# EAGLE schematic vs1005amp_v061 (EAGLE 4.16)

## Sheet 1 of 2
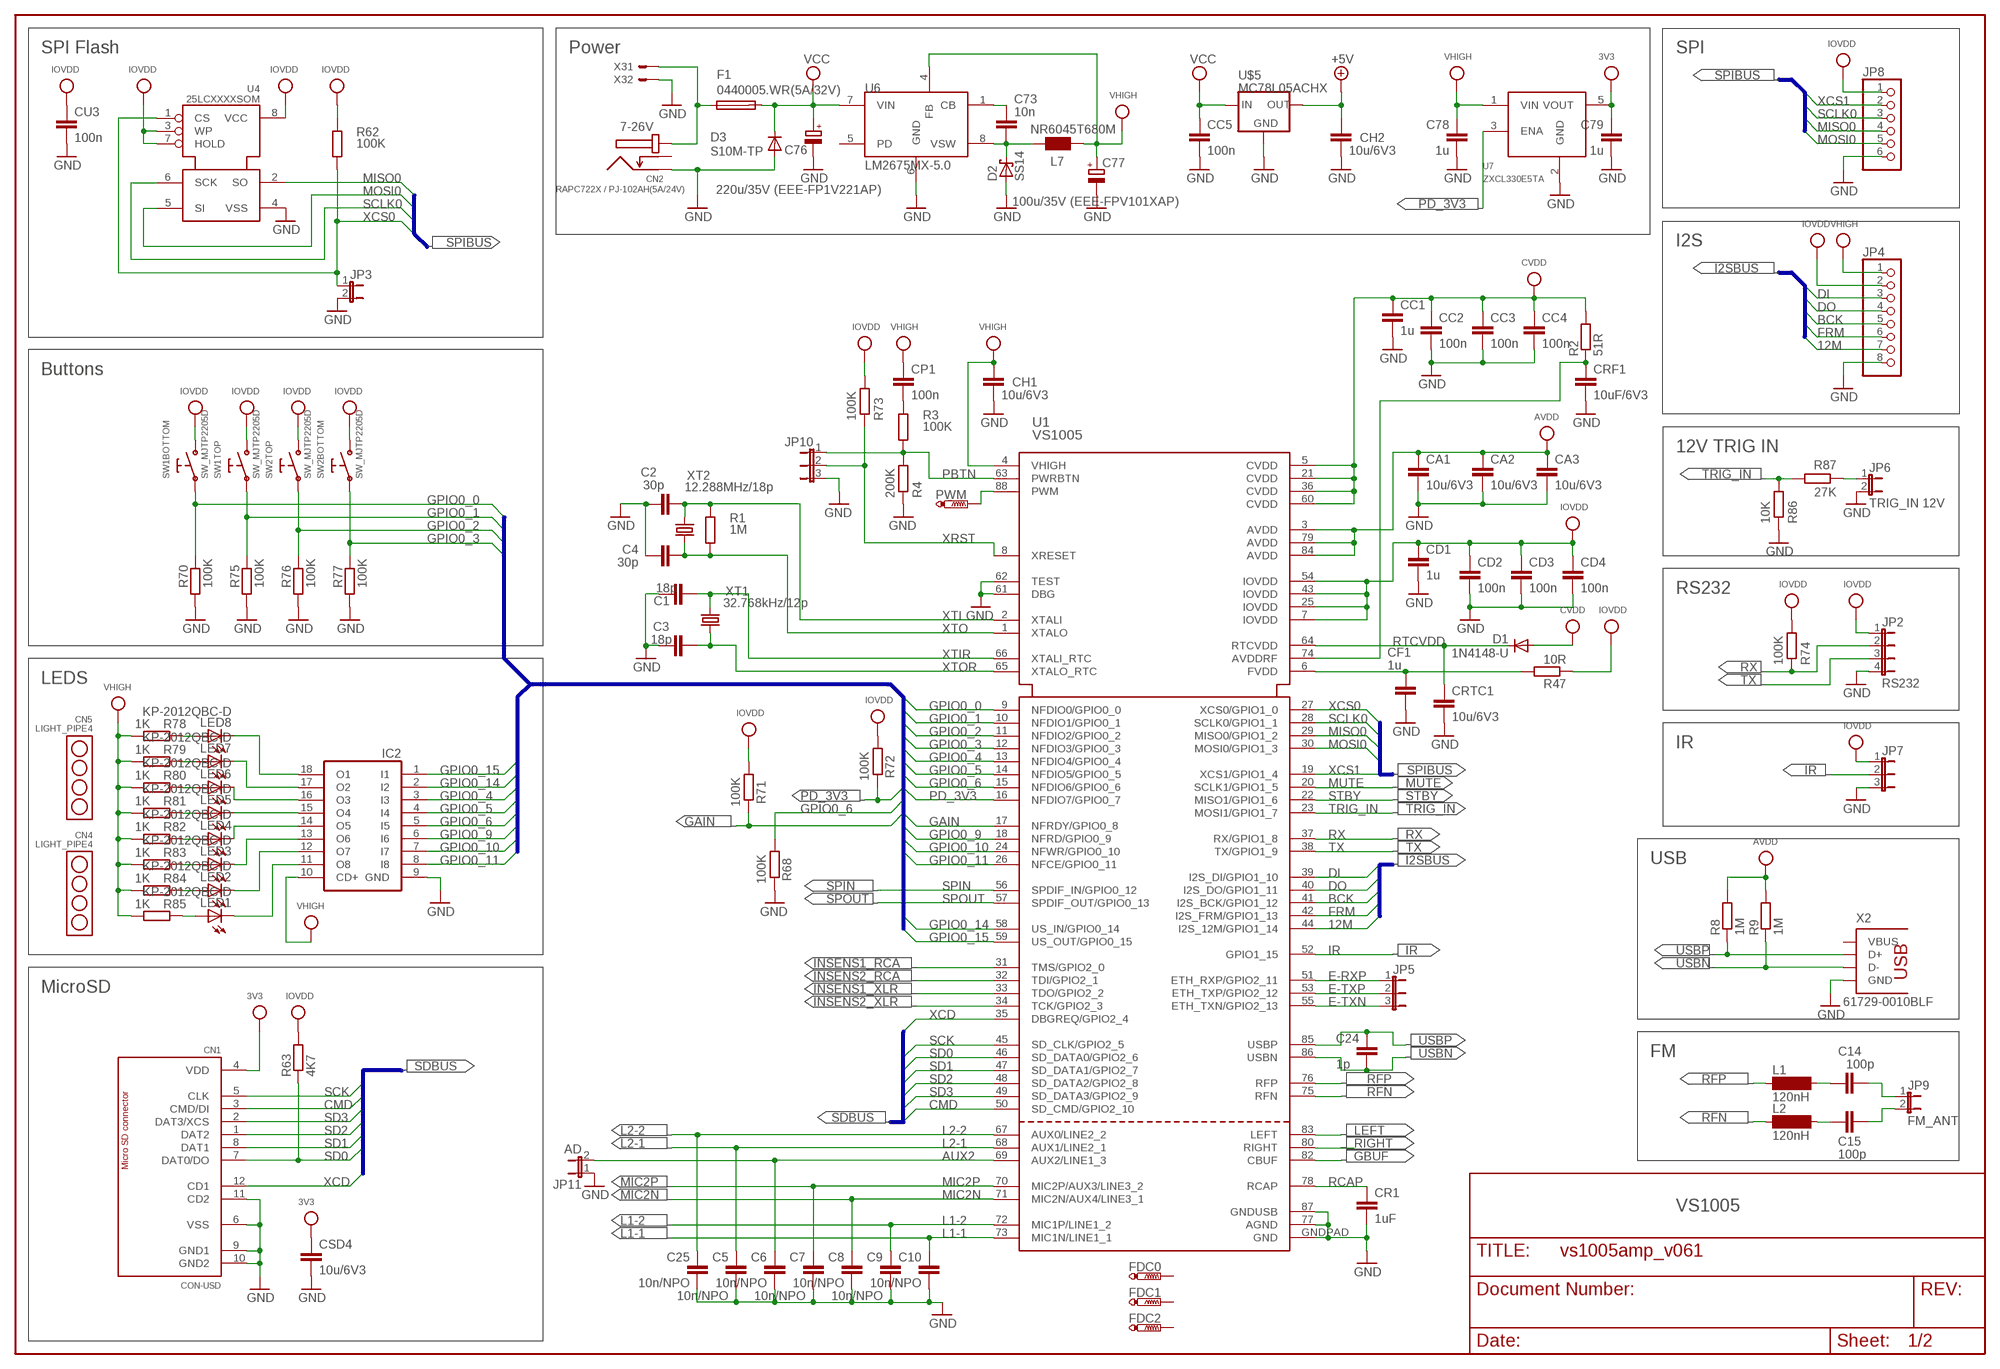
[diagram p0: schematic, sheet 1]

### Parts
C1  18p  C-EUC0603  [C0603]
C2  30p  C-EUC0603  [C0603]
C3  18p  C-EUC0603  [C0603]
C4  30p  C-EUC0603  [C0603]
C5  10n/NPO  C-EUC0805  [C0805]
C6  10n/NPO  C-EUC0805  [C0805]
C7  10n/NPO  C-EUC0805  [C0805]
C8  10n/NPO  C-EUC0805  [C0805]
C9  10n/NPO  C-EUC0805  [C0805]
C10  10n/NPO  C-EUC0805  [C0805]
C14  100p  C-EUC0603  [C0603]
C15  100p  C-EUC0603  [C0603]
C24  1p  C-EUC0603  [C0603]
C25  10n/NPO  C-EUC0805  [C0805]
C73  10n  C-EUC0603  [C0603]
C76  220u/35V (EEE-FP1V221AP)  CPOL-EUF  [PANASONIC_F]
C77  100u/35V (EEE-FPV101XAP)  CPOL-EUD  [PANASONIC_D]
C78  1u  C-EUC0603  [C0603]
C79  1u  C-EUC0603  [C0603]
CA1  10u/6V3  C-EUC0603  [C0603]
CA2  10u/6V3  C-EUC0603  [C0603]
CA3  10u/6V3  C-EUC0603  [C0603]
CC1  1u  C-EUC0603  [C0603]
CC2  100n  C-EUC0603  [C0603]
CC3  100n  C-EUC0603  [C0603]
CC4  100n  C-EUC0603  [C0603]
CC5  100n  C-EUC0603  [C0603]
CD1  1u  C-EUC0603  [C0603]
CD2  100n  C-EUC0603  [C0603]
CD3  100n  C-EUC0603  [C0603]
CD4  100n  C-EUC0603  [C0603]
CF1  1u  C-EUC0603  [C0603]
CH1  10u/6V3  C-EUC0603  [C0603]
CH2  10u/6V3  C-EUC0603  [C0603]
CN1  CON-USD  [MSSN09-A0-300]
CN2  RAPC722X / PJ-102AH(5A/24V)  CON_DC-JACK  [DC-JACK]
CN4  LIGHT_PIPE4  [LIGHT_PIPE4]
CN5  LIGHT_PIPE4  [LIGHT_PIPE4]
CP1  100n  C-EUC0603  [C0603]
CR1  1uF  C-EUC0603  [C0603]
CRF1  10uF/6V3  C-EUC0603  [C0603]
CRTC1  10u/6V3  C-EUC0603  [C0603]
CSD4  10u/6V3  C-EUC0603  [C0603]
CU3  100n  C-EUC0603  [C0603]
D1  1N4148-U  [MICROMELF-W]
D2  SS14  SS12-SMA  [DO214AC]
D3  S10M-TP  DIODE-DO214BA  [DO214BA]
F1  0440005.WR(5A/32V)  FUSE_1206  [R1206]
FDC0  PTR1TP10R  [TP10R]
FDC1  PTR1TP10R  [TP10R]
FDC2  PTR1TP10R  [TP10R]
IC2  ULN2803AADWR  [SO18L]
JP2  RS232  JP4E  [JP4]
JP3  JP1E  [JP1]
JP4  PINHD-1X8  [1X08]
JP5  JP2E  [JP2]
JP6  TRIG_IN 12V  JP1E  [JP1]
JP7  JP2E  [JP2]
JP8  PINHD-1X6  [1X06]
JP9  FM_ANT  JP1E  [JP1]
JP10  JP2E  [JP2]
JP11  AD  JP1E  [JP1]
L1  120nH  SM-0603  [0603]
L2  120nH  SM-0603  [0603]
L7  NR6045T680M  L_NR6045  [L_NR6045]
LED1  KP-2012QBC-D  LEDCHIPLED_0805  [CHIPLED_0805]
LED2  KP-2012QBC-D  LEDCHIPLED_0805  [CHIPLED_0805]
LED3  KP-2012QBC-D  LEDCHIPLED_0805  [CHIPLED_0805]
LED4  KP-2012QBC-D  LEDCHIPLED_0805  [CHIPLED_0805]
LED5  KP-2012QBC-D  LEDCHIPLED_0805  [CHIPLED_0805]
LED6  KP-2012QBC-D  LEDCHIPLED_0805  [CHIPLED_0805]
LED7  KP-2012QBC-D  LEDCHIPLED_0805  [CHIPLED_0805]
LED8  KP-2012QBC-D  LEDCHIPLED_0805  [CHIPLED_0805]
PWM  PTR1TP10R  [TP10R]
R1  1M  R-EU_R0603  [R0603]
R2  51R  R-EU_R0603  [R0603]
R3  100K  R-EU_R0603  [R0603]
R4  200K  R-EU_R0603  [R0603]
R8  1M  R-EU_R0603  [R0603]
R9  1M  R-EU_R0603  [R0603]
R47  10R  R-EU_R0603  [R0603]
R62  100K  R-EU_R0603  [R0603]
R63  4K7  R-EU_R0603  [R0603]
R68  100K  R-EU_R0603  [R0603]
R70  100K  R-EU_R0603  [R0603]
R71  100K  R-EU_R0603  [R0603]
R72  100K  R-EU_R0603  [R0603]
R73  100K  R-EU_R0603  [R0603]
R74  100K  R-EU_R0603  [R0603]
R75  100K  R-EU_R0603  [R0603]
R76  100K  R-EU_R0603  [R0603]
R77  100K  R-EU_R0603  [R0603]
R78  1K  R-EU_R0603  [R0603]
R79  1K  R-EU_R0603  [R0603]
R80  1K  R-EU_R0603  [R0603]
R81  1K  R-EU_R0603  [R0603]
R82  1K  R-EU_R0603  [R0603]
R83  1K  R-EU_R0603  [R0603]
R84  1K  R-EU_R0603  [R0603]
R85  1K  R-EU_R0603  [R0603]
R86  10K  R-EU_R0603  [R0603]
R87  27K  R-EU_R0603  [R0603]
SW1  SW_MJTP2205D  [SW_MJTP2205D]
SW2  SW_MJTP2205D  [SW_MJTP2205D]
U1  VS1005  [QFN88_2]
U4  25LCXXXXSOM  [SO-8MN]
U6  LM2675MX-5.0  LM2675  [SO08]
U7  ZXCL330E5TA  ZXCL280E5TA  [SOT23-5L]
U$5  MC78L05ACHX  UA78LXX  [SOT89]
X2  61729-0010BLF  CON_USB_B@N  [PN61729]
X3  1935161  TER_BLOCK_2WAY  [TER_BLOCK-2-WAY]
XT1  32.768kHz/12p  CRYSTAL3.2X1.5MM  [CRYSTAL_1206]
XT2  12.288MHz/18p  CRYTALHC49UP  [HC49UP]

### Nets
1: CN2.1 F1.1 X3.P$1
3V3: C79.1 CN1.4(VDD) CSD4.1 U7.5(VOUT) ; also sheet 2
12M: JP4.7 U1.44(I2S_12M/GPIO1_14)
+5V: CH2.1 U$5.1(OUT) ; also sheet 2
AUX2: C6.1 JP11.2 U1.69(AUX2/LINE1_3)
AVDD: CA1.1 CA2.1 CA3.1 R8.2 R9.2 U1.3(AVDD) U1.79(AVDD) U1.84(AVDD) ; also sheet 2
AVDDRF: CRF1.1 R2.1 U1.74(AVDDRF)
BCK: JP4.5 U1.41(I2S_BCK/GPIO1_12)
CMD: CN1.3(CMD/DI) U1.50(SD_CMD/GPIO2_10)
CVDD: CC1.1 CC2.1 CC3.1 CC4.1 D1.A R2.2 U1.5(CVDD) U1.21(CVDD) U1.36(CVDD) U1.60(CVDD)
DI: JP4.3 U1.39(I2S_DI/GPIO1_10)
DO: JP4.4 U1.40(I2S_DO/GPIO1_11)
E-RXP: JP5.1 U1.51(ETH_RXP/GPIO2_11)
E-TXN: JP5.3 U1.55(ETH_TXN/GPIO2_13)
E-TXP: JP5.2 U1.53(ETH_TXP/GPIO2_12)
FRM: JP4.6 U1.42(I2S_FRM/GPIO1_13)
FVDD: CF1.1 R47.2 U1.6(FVDD)
GAIN: R71.2 U1.17(NFRDY/GPIO0_8) ; also sheet 2
GBUF: U1.82(CBUF) ; also sheet 2
GND: C1.1 C2.1 C3.1 C4.1 C5.2 C6.2 C7.2 C8.2 C9.2 C10.2 C25.2 C76.- C77.- C78.2 C79.2 CA1.2 CA2.2 CA3.2 CC1.2 CC2.2 CC3.2 CC4.2 CC5.2 CD1.2 CD2.2 CD3.2 CD4.2 CF1.2 CH1.2 CH2.2 CN1.6(VSS) CN1.9(GND1) CN1.10(GND2) CN1.11(CD2) CN2.3 CR1.2 CRF1.2 CRTC1.2 CSD4.2 CU3.2 D2.A D3.A IC2.9(GND) JP2.4 JP3.2 JP4.8 JP6.2 JP7.3 JP8.6 JP10.3 JP11.1 R4.2 R68.1 R70.2 R75.2 R76.2 R77.2 R86.2 U1.61(DBG) U1.62(TEST) U1.77(AGND) U1.87(GNDUSB) U1.GNDPAD(GND) U4.4(VSS) U6.6(GND) U7.2(GND) U$5.2(GND) X2.4(GND) X3.P$2 ; also sheet 2
GPIO0_0: R70.1 SW1.2 U1.9(NFDIO0/GPIO0_0)
GPIO0_1: R75.1 SW1.1 U1.10(NFDIO1/GPIO0_1)
GPIO0_2: R76.1 SW2.1 U1.11(NFDIO2/GPIO0_2)
GPIO0_3: R77.1 SW2.2 U1.12(NFDIO3/GPIO0_3)
GPIO0_4: IC2.3(I3) U1.13(NFDIO4/GPIO0_4)
GPIO0_5: IC2.4(I4) U1.14(NFDIO5/GPIO0_5)
GPIO0_6: IC2.5(I5) R68.2 U1.15(NFDIO6/GPIO0_6)
GPIO0_9: IC2.6(I6) U1.18(NFRD/GPIO0_9)
GPIO0_10: IC2.7(I7) U1.24(NFWR/GPIO0_10)
GPIO0_11: IC2.8(I8) U1.26(NFCE/GPIO0_11)
GPIO0_14: IC2.2(I2) U1.58(US_IN/GPIO0_14)
GPIO0_15: IC2.1(I1) U1.59(US_OUT/GPIO0_15)
INSENS1_RCA: U1.31(TMS/GPIO2_0) ; also sheet 2
INSENS1_XLR: U1.33(TDO/GPIO2_2) ; also sheet 2
INSENS2_RCA: U1.32(TDI/GPIO2_1) ; also sheet 2
INSENS2_XLR: U1.34(TCK/GPIO2_3) ; also sheet 2
IOVDD: CD1.1 CD2.1 CD3.1 CD4.1 CU3.1 JP2.1 JP4.2 JP7.1 JP8.1 R47.1 R62.1 R63.2 R71.1 R72.1 R73.1 R74.1 SW1.3 SW1.4 SW2.3 SW2.4 U1.7(IOVDD) U1.25(IOVDD) U1.43(IOVDD) U1.54(IOVDD) U4.3(WP) U4.7(HOLD) U4.8(VCC)
IR: JP7.2 U1.52(GPIO1_15)
L1-1: C10.1 U1.73(MIC1N/LINE1_1) ; also sheet 2
L1-2: C9.1 U1.72(MIC1P/LINE1_2) ; also sheet 2
L2-1: C5.1 U1.68(AUX1/LINE2_1) ; also sheet 2
L2-2: C25.1 U1.67(AUX0/LINE2_2) ; also sheet 2
LEFT: U1.83(LEFT) ; also sheet 2
MIC2N: C8.1 U1.71(MIC2N/AUX4/LINE3_1) ; also sheet 2
MIC2P: C7.1 U1.70(MIC2P/AUX3/LINE3_2) ; also sheet 2
MISO0: JP8.4 U1.29(MISO0/GPIO1_2) U4.2(SO)
MOSI0: JP8.5 U1.30(MOSI0/GPIO1_3) U4.5(SI)
MUTE: U1.20(SCLK1/GPIO1_5) ; also sheet 2
N$1: C14.1 L1.2
N$3: CP1.2 R3.1
N$28: LED8.A R78.2
N$60: C14.2 JP9.1
N$67: C73.1 U6.1(CB)
N$68: C73.2 D2.C L7.1 U6.8(VSW)
N$69: LED7.A R79.2
N$70: LED6.A R80.2
N$72: LED5.A R81.2
N$73: LED4.A R82.2
N$75: LED3.A R83.2
N$76: LED2.A R84.2
N$77: LED1.A R85.2
N$78: IC2.11(O8) LED1.C
N$79: IC2.12(O7) LED2.C
N$81: IC2.13(O6) LED3.C
N$82: IC2.14(O5) LED4.C
N$83: IC2.15(O4) LED5.C
N$84: IC2.16(O3) LED6.C
N$85: IC2.17(O2) LED7.C
N$86: IC2.18(O1) LED8.C
N$87: JP6.1 R87.2
N$88: C15.2 JP9.2
N$103: C15.1 L2.2
PBTN: JP10.1 R3.2 R4.1 U1.63(PWRBTN)
PD_3V3: R72.2 U1.16(NFDIO7/GPIO0_7) U7.3(ENA)
PWM: PWM.TP U1.88(PWM)
RCAP: CR1.1 U1.78(RCAP) ; also sheet 2
RFN: L2.1 U1.75(RFN)
RFP: L1.1 U1.76(RFP)
RIGHT: U1.80(RIGHT) ; also sheet 2
RTCVDD: CRTC1.1 D1.C U1.64(RTCVDD)
RX: JP2.2 R74.2 U1.37(RX/GPIO1_8)
SCK: CN1.5(CLK) U1.45(SD_CLK/GPIO2_5)
SCLK0: JP8.3 U1.28(SCLK0/GPIO1_1) U4.6(SCK)
SD0: CN1.7(DAT0/DO) R63.1 U1.46(SD_DATA0/GPIO2_6)
SD1: CN1.8(DAT1) U1.47(SD_DATA1/GPIO2_7)
SD2: CN1.1(DAT2) U1.48(SD_DATA2/GPIO2_8)
SD3: CN1.2(DAT3/XCS) U1.49(SD_DATA3/GPIO2_9)
SPIN: U1.56(SPDIF_IN/GPIO0_12) ; also sheet 2
SPOUT: U1.57(SPDIF_OUT/GPIO0_13) ; also sheet 2
STBY: U1.22(MISO1/GPIO1_6) ; also sheet 2
TRIG_IN: R86.1 R87.1 U1.23(MOSI1/GPIO1_7)
TX: JP2.3 U1.38(TX/GPIO1_9)
USBN: C24.2 R9.1 U1.86(USBN) X2.2(D-)
USBP: C24.1 R8.1 U1.85(USBP) X2.3(D+)
VCC: C76.+ CC5.1 D3.C F1.2 U6.7(VIN) U$5.3(IN) ; also sheet 2
VHIGH: C77.+ C78.1 CH1.1 CP1.1 IC2.10(CD+) JP4.1 L7.2 R78.1 R79.1 R80.1 R81.1 R82.1 R83.1 R84.1 R85.1 U1.4(VHIGH) U6.4(FB) U7.1(VIN)
XCD: CN1.12(CD1) U1.35(DBGREQ/GPIO2_4)
XCS0: JP3.1 R62.2 U1.27(XCS0/GPIO1_0) U4.1(CS)
XCS1: JP8.2 U1.19(XCS1/GPIO1_4)
XRST: JP10.2 R73.2 U1.8(XRESET)
XTI: C2.2 R1.1 U1.2(XTALI) XT2.2
XTIR: C1.2 U1.66(XTALI_RTC) XT1.2
XTO: C4.2 R1.2 U1.1(XTALO) XT2.1
XTOR: C3.2 U1.65(XTALO_RTC) XT1.1
Unconnected: CN2.2 FDC0.TP FDC1.TP FDC2.TP U6.5(PD) X2.1(VBUS)

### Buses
NFBUS:GPIO0_[0..11],GPIO0_[14..15]
SDBUS:SCK,SD[0..3],CMD,XCD
SPIBUS:XCS1,XCS0,SCLK0,MISO0,MOSI0
I2SBUS:DI,DO,BCK,FRM,12M

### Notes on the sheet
- SPI Flash | Power | SPI
- SPIBUS
- 7-26V
- SPIBUS
- I2S
- I2SBUS
- Buttons
- 12V TRIG IN
- RS232
- LEDS
- IR
- SPIBUS
- I2SBUS | USB
- MicroSD
- FM
- SDBUS
- SDBUS
- VS1005

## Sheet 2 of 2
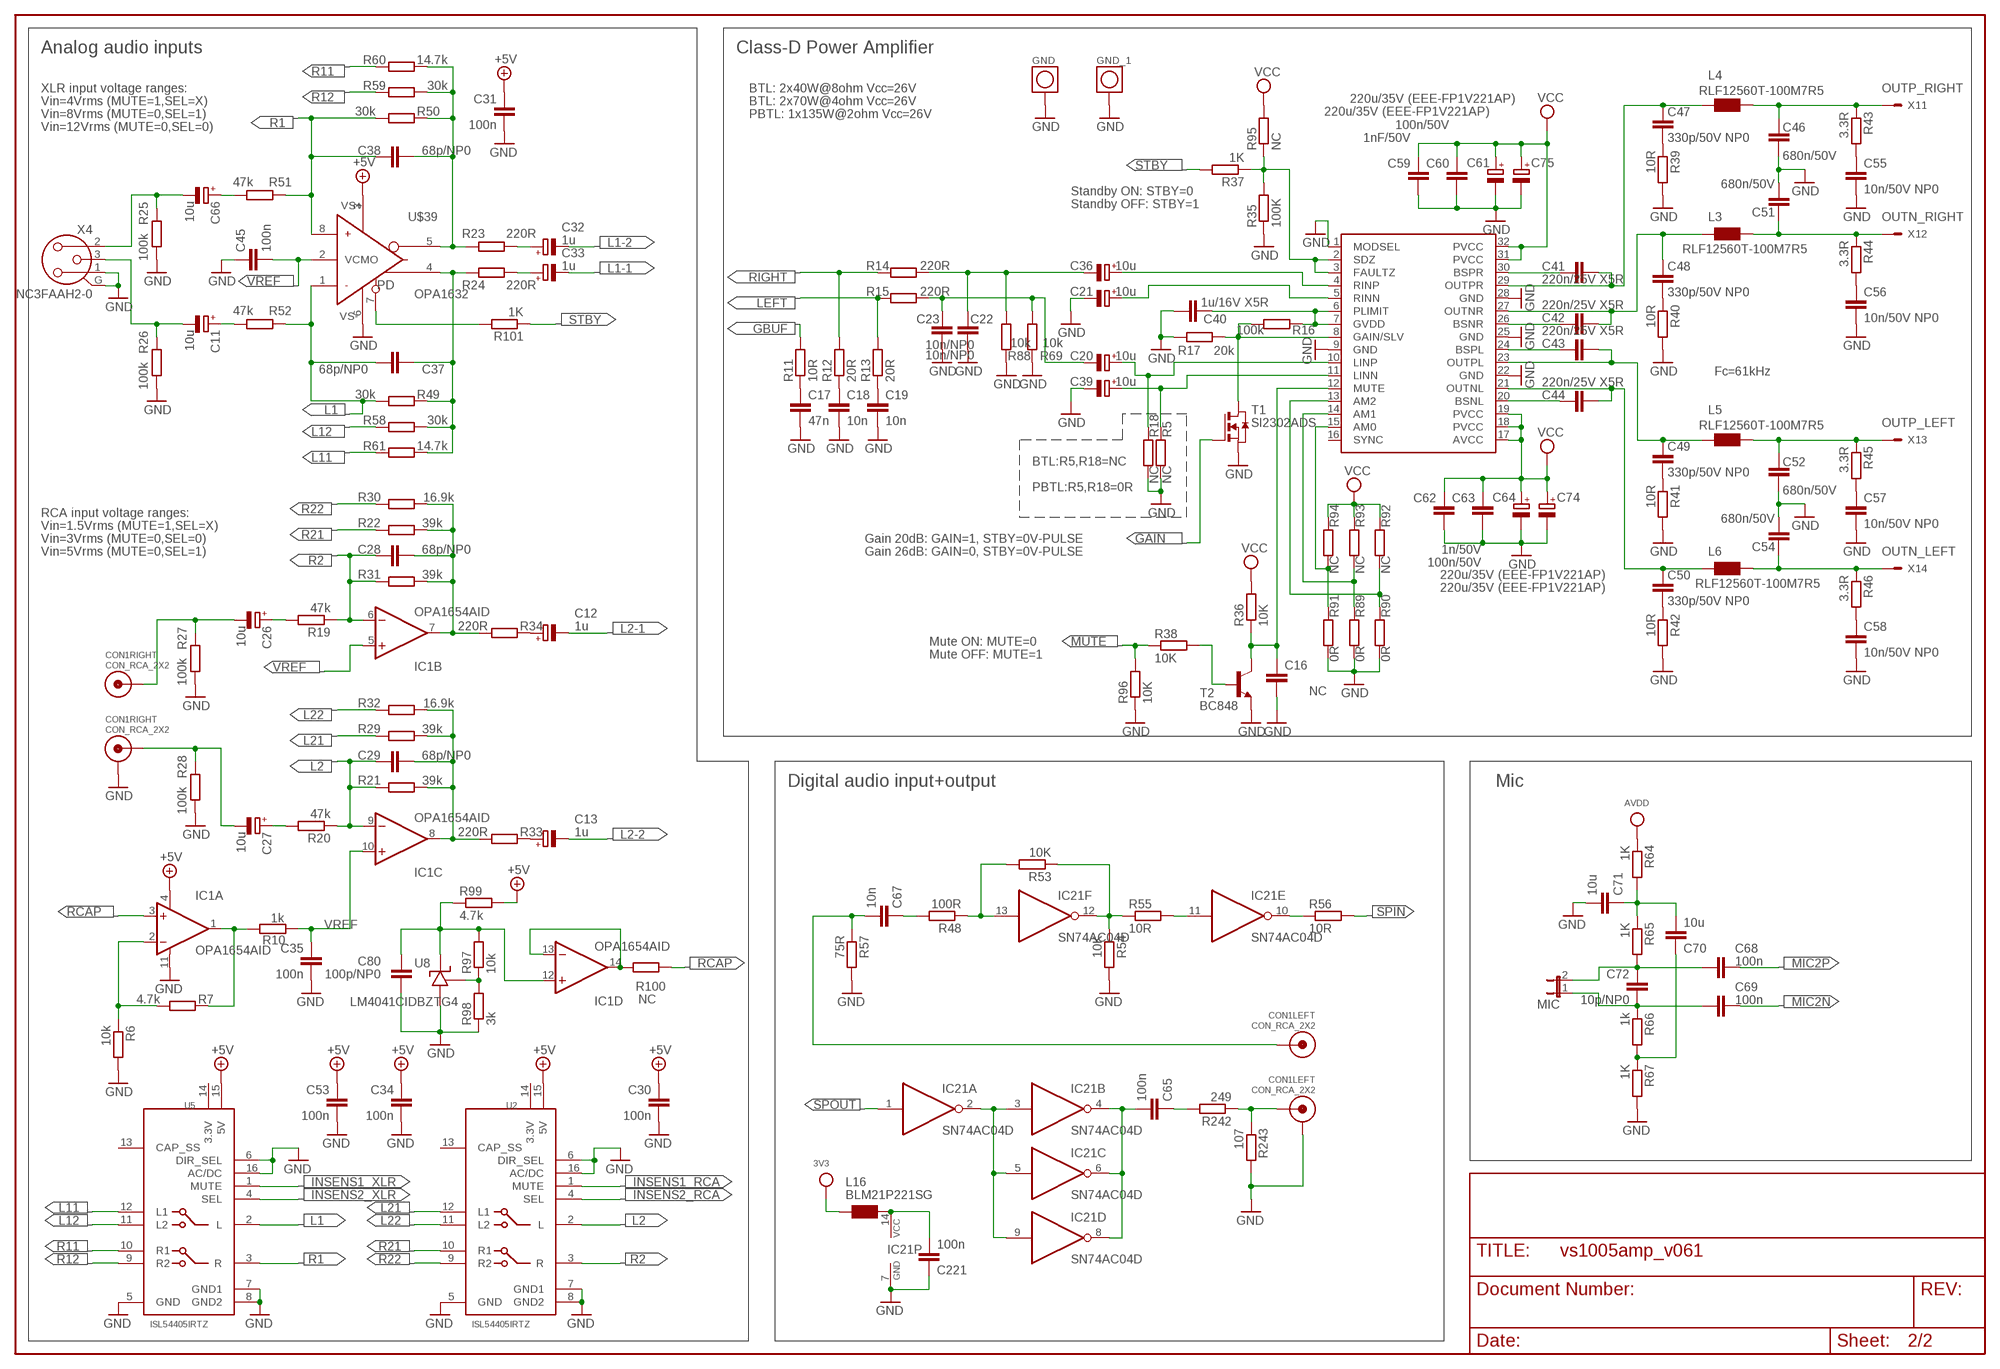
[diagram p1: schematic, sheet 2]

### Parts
C11  10u  CPOL-EUB  [PANASONIC_B]
C12  1u  CPOL-EU153CLV-0405  [153CLV-0405]
C13  1u  CPOL-EU153CLV-0405  [153CLV-0405]
C16  NC  C-EUC0603  [C0603]
C17  47n  C-EUC0603  [C0603]
C18  10n  C-EUC0603  [C0603]
C19  10n  C-EUC0603  [C0603]
C20  10u  CPOL-EUB  [PANASONIC_B]
C21  10u  CPOL-EUB  [PANASONIC_B]
C22  10n/NP0  C-EUC0805  [C0805]
C23  10n/NP0  C-EUC0805  [C0805]
C26  10u  CPOL-EUB  [PANASONIC_B]
C27  10u  CPOL-EUB  [PANASONIC_B]
C28  68p/NP0  C-EUC0805  [C0805]
C29  68p/NP0  C-EUC0805  [C0805]
C30  100n  C-EUC0603  [C0603]
C31  100n  C-EUC0603  [C0603]
C32  1u  CPOL-EU153CLV-0405  [153CLV-0405]
C33  1u  CPOL-EU153CLV-0405  [153CLV-0405]
C34  100n  C-EUC0603  [C0603]
C35  100n  C-EUC0603  [C0603]
C36  10u  CPOL-EUB  [PANASONIC_B]
C37  68p/NP0  C-EUC0805  [C0805]
C38  68p/NP0  C-EUC0805  [C0805]
C39  10u  CPOL-EUB  [PANASONIC_B]
C40  1u/16V X5R  C-EUC0603  [C0603]
C41  220n/25V X5R  C-EUC0603  [C0603]
C42  220n/25V X5R  C-EUC0603  [C0603]
C43  220n/25V X5R  C-EUC0603  [C0603]
C44  220n/25V X5R  C-EUC0603  [C0603]
C45  100n  C-EUC0603  [C0603]
C46  680n/50V  C-EUC1206  [C1206]
C47  330p/50V NP0  C-EUC0603  [C0603]
C48  330p/50V NP0  C-EUC0603  [C0603]
C49  330p/50V NP0  C-EUC0603  [C0603]
C50  330p/50V NP0  C-EUC0603  [C0603]
C51  680n/50V  C-EUC1206  [C1206]
C52  680n/50V  C-EUC1206  [C1206]
C53  100n  C-EUC0603  [C0603]
C54  680n/50V  C-EUC1206  [C1206]
C55  10n/50V NP0  C-EUC0805  [C0805]
C56  10n/50V NP0  C-EUC0805  [C0805]
C57  10n/50V NP0  C-EUC0805  [C0805]
C58  10n/50V NP0  C-EUC0805  [C0805]
C59  1nF/50V  C-EUC0603  [C0603]
C60  100n/50V  C-EUC0603  [C0603]
C61  220u/35V (EEE-FP1V221AP)  CPOL-EUF  [PANASONIC_F]
C62  1n/50V  C-EUC0603  [C0603]
C63  100n/50V  C-EUC0603  [C0603]
C64  220u/35V (EEE-FP1V221AP)  CPOL-EUF  [PANASONIC_F]
C65  100n  C-EUC0603  [C0603]
C66  10u  CPOL-EUB  [PANASONIC_B]
C67  10n  C-EUC0603  [C0603]
C68  100n  C-EUC0603  [C0603]
C69  100n  C-EUC0603  [C0603]
C70  10u  C-EUC0805  [C0805]
C71  10u  C-EUC0805  [C0805]
C72  10p/NP0  C-EUC0603  [C0603]
C74  220u/35V (EEE-FP1V221AP)  CPOL-EUF  [PANASONIC_F]
C75  220u/35V (EEE-FP1V221AP)  CPOL-EUF  [PANASONIC_F]
C80  100p/NP0  C-EUC0603K  [C0603K]
C221  100n  C-EUC0603  [C0603]
CON1  CON_RCA_2X2  [4XRCA_2X2]
GND  MEAS_PIN  [MEAS_PIN]
GND_1  MEAS_PIN  [MEAS_PIN]
IC1  OPA1654AID  OPA4132U  [SO14]
IC21  SN74AC04D  74AC04D  [SO14]
L3  RLF12560T-100M7R5  L_12560  [RLF12560]
L4  RLF12560T-100M7R5  L_12560  [RLF12560]
L5  RLF12560T-100M7R5  L_12560  [RLF12560]
L6  RLF12560T-100M7R5  L_12560  [RLF12560]
L16  BLM21P221SG  WE-KI_0805_B  [WE-KI_0805_B]
MIC  JP1E  [JP1]
R5  NC  R-EU_R0603  [R0603]
R6  10k  R-EU_R0603  [R0603]
R7  4.7k  R-EU_R0603  [R0603]
R10  1k  R-EU_R0603  [R0603]
R11  10R  R-EU_R0603  [R0603]
R12  20R  R-EU_R0603  [R0603]
R13  20R  R-EU_R0603  [R0603]
R14  220R  R-EU_R0603  [R0603]
R15  220R  R-EU_R0603  [R0603]
R16  100k  R-EU_R0603  [R0603]
R17  20k  R-EU_R0603  [R0603]
R18  NC  R-EU_R0603  [R0603]
R19  47k  R-EU_R0603  [R0603]
R20  47k  R-EU_R0603  [R0603]
R21  39k  R-EU_R0603  [R0603]
R22  39k  R-EU_R0603  [R0603]
R23  220R  R-EU_R0603  [R0603]
R24  220R  R-EU_R0603  [R0603]
R25  100k  R-EU_R0603  [R0603]
R26  100k  R-EU_R0603  [R0603]
R27  100k  R-EU_R0603  [R0603]
R28  100k  R-EU_R0603  [R0603]
R29  39k  R-EU_R0603  [R0603]
R30  16.9k  R-EU_R0603  [R0603]
R31  39k  R-EU_R0603  [R0603]
R32  16.9k  R-EU_R0603  [R0603]
R33  220R  R-EU_R0603  [R0603]
R34  220R  R-EU_R0603  [R0603]
R35  100K  R-EU_R0603  [R0603]
R36  10K  R-EU_R0603  [R0603]
R37  1K  R-EU_R0603  [R0603]
R38  10K  R-EU_R0603  [R0603]
R39  10R  R-EU_R0805  [R0805]
R40  10R  R-EU_R0805  [R0805]
R41  10R  R-EU_R0805  [R0805]
R42  10R  R-EU_R0805  [R0805]
R43  3.3R  R-EU_R0805  [R0805]
R44  3.3R  R-EU_R0805  [R0805]
R45  3.3R  R-EU_R0805  [R0805]
R46  3.3R  R-EU_R0805  [R0805]
R48  100R  R-EU_R0603  [R0603]
R49  30k  R-EU_R0603  [R0603]
R50  30k  R-EU_R0603  [R0603]
R51  47k  R-EU_R0603  [R0603]
R52  47k  R-EU_R0603  [R0603]
R53  10K  R-EU_R0603  [R0603]
R54  10K  R-EU_R0603  [R0603]
R55  10R  R-EU_R0603  [R0603]
R56  10R  R-EU_R0603  [R0603]
R57  75R  R-EU_R0603  [R0603]
R58  30k  R-EU_R0603  [R0603]
R59  30k  R-EU_R0603  [R0603]
R60  14.7k  R-EU_R0603  [R0603]
R61  14.7k  R-EU_R0603  [R0603]
R64  1K  R-EU_R0603  [R0603]
R65  1K  R-EU_R0603  [R0603]
R66  1k  R-EU_R0603  [R0603]
R67  1K  R-EU_R0603  [R0603]
R69  10k  R-EU_R0603  [R0603]
R88  10k  R-EU_R0603  [R0603]
R89  0R  R-EU_R0603  [R0603]
R90  0R  R-EU_R0603  [R0603]
R91  0R  R-EU_R0603  [R0603]
R92  NC  R-EU_R0603  [R0603]
R93  NC  R-EU_R0603  [R0603]
R94  NC  R-EU_R0603  [R0603]
R95  NC  R-EU_R0603  [R0603]
R96  10K  R-EU_R0603  [R0603]
R97  10k  R-EU_R0603  [R0603]
R98  3k  R-EU_R0603  [R0603]
R99  4.7k  R-EU_R0603  [R0603]
R100  NC  R-EU_R0603  [R0603]
R101  1K  R-EU_R0603  [R0603]
R242  249  R-EU_R1206  [R1206]
R243  107  R-EU_R1206  [R1206]
T1  SI2302ADS  [SOT23]
T2  BC848  [SOT23]
U2  ISL54405IRTZ  ISL54405  [QFN16]
U3  TPA3116D2  [HTSSOP32]
U5  ISL54405IRTZ  ISL54405  [QFN16]
U8  LM4041CIDBZTG4  LM4041CI  [SOT23@1]
U$39  OPA1632  THS4130  [SO08]
X1  1935187  TER_BLOCK_4WAY  [TER_BLOCK-4-WAY]
X4  NC3FAAH2-0  NC3FAH2  [NC3FAH2]

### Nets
3V3: L16.1 ; also sheet 1
+5V: C30.1 C31.1 C34.1 C53.1 IC1.4(A:V+) R99.2 U2.15(5V) U5.15(5V) U$39.3(VS+) ; also sheet 1
AVDD: R64.1 ; also sheet 1
GAIN: T1.1(G) ; also sheet 1
GBUF: R11.2 ; also sheet 1
GND: C16.2 C17.2 C18.2 C19.2 C21.- C22.2 C23.2 C30.2 C31.2 C34.2 C35.2 C39.- C40.2 C45.1 C46.2 C51.2 C52.2 C53.2 C54.2 C55.2 C56.2 C57.2 C58.2 C59.2 C60.2 C61.- C62.2 C63.2 C64.- C71.2 C74.- C75.- C80.2 C221.1 CON1.GL(LEFT:RING) CON1.GR(RIGHT:RING) GND.P$1 GND_1.P$1 IC1.11(A:V-) IC21.7(P:GND) R5.2 R6.2 R17.2 R18.2 R25.1 R26.1 R27.1 R28.1 R35.1 R39.2 R40.2 R41.2 R42.2 R54.2 R57.2 R67.2 R69.2 R88.2 R89.2 R90.2 R91.2 R96.1 R98.1 R243.2 T1.2(S) T2.2(E) U2.5(GND) U2.6(DIR_SEL) U2.7(GND1) U2.8(GND2) U2.16(AC/DC) U3.1(MODSEL) U3.9(GND) U3.22(GND) U3.25(GND) U3.28(GND) U5.5(GND) U5.6(DIR_SEL) U5.7(GND1) U5.8(GND2) U5.16(AC/DC) U8.3(A) U$39.6(VS-) X4.1 X4.G ; also sheet 1
INSENS1_RCA: U2.1(MUTE) ; also sheet 1
INSENS1_XLR: U5.1(MUTE) ; also sheet 1
INSENS2_RCA: U2.4(SEL) ; also sheet 1
INSENS2_XLR: U5.4(SEL) ; also sheet 1
L1: C37.2 R49.1 R52.2 U5.2(L) U$39.1(-IN)
L1-1: C33.- ; also sheet 1
L1-2: C32.- ; also sheet 1
L2: C29.1 IC1.9(C:-IN) R20.1 R21.2 U2.2(L)
L2-1: C12.- ; also sheet 1
L2-2: C13.- ; also sheet 1
L11: R61.2 U5.12(L1)
L12: R58.2 U5.11(L2)
L21: R29.2 U2.12(L1)
L22: R32.2 U2.11(L2)
L222: C37.1 R24.1 R49.2 R58.1 R61.1 U$39.4(+OUT)
LEFT: R13.2 R15.2 ; also sheet 1
MIC2N: C69.1 ; also sheet 1
MIC2P: C68.1 ; also sheet 1
MUTE: R38.1 R96.2 ; also sheet 1
N$2: C27.+ R20.2
N$4: C26.+ R19.2
N$6: C29.2 IC1.8(C:OUT) R21.1 R29.1 R32.1 R33.1
N$7: C28.2 IC1.7(B:OUT) R22.1 R30.1 R31.1 R34.1
N$8: C66.- R25.2 X4.2
N$9: C11.- R26.2 X4.3
N$11: C32.+ R23.2
N$12: R38.2 T2.1(B)
N$13: R97.1 R98.2 U8.1(FB)
N$14: C33.+ R24.2
N$15: R101.2 U$39.7
N$16: R35.2 R37.1 R95.1 U3.2(SDZ) U3.3(FAULTZ)
N$17: C26.- CON1.WR(RIGHT:TIP1) R27.2
N$18: C19.1 R13.1
N$19: C27.- CON1.RR(RIGHT:TIP) R28.2
N$20: C13.+ R33.2
N$21: C18.1 R12.1
N$22: C17.1 R11.1
N$23: C12.+ R34.2
N$24: C69.2 C72.2 MIC.1 R66.1
N$26: C68.2 C72.1 MIC.2 R65.2
N$27: C70.2 C71.1 R64.2 R65.1
N$29: C21.+ U3.5(RINN)
N$30: IC1.2(A:-IN) R6.1 R7.1
N$31: C36.+ U3.4(RINP)
N$32: C16.1 R36.1 T2.3(C) U3.12(MUTE)
N$33: IC1.1(A:OUT) R7.2 R10.1
N$34: C70.1 R66.2 R67.1
N$35: R16.2 R17.1 T1.3(D) U3.8(GAIN/SLV)
N$36: C80.1 IC1.12(D:+IN) R97.2 R99.1 U8.2(C)
N$37: C41.2 U3.30(BSPR)
N$38: C42.2 U3.26(BSNR)
N$39: C42.1 C48.1 L3.1 U3.27(OUTNR)
N$40: IC1.13(D:-IN) IC1.14(D:OUT) R100.1
N$41: C43.2 U3.24(BSPL)
N$42: C43.1 C49.1 L5.1 U3.23(OUTPL)
N$43: C44.1 C50.1 L6.1 U3.21(OUTNL)
N$44: C44.2 U3.20(BSNL)
N$45: C40.1 R16.1 U3.6(PLIMIT) U3.7(GVDD)
N$46: IC21.2(A:O) IC21.3(B:I) IC21.5(C:I) IC21.9(D:I)
N$47: C20.- C23.1 R15.1 R69.1
N$49: C47.2 R39.1
N$50: C48.2 R40.1
N$51: C49.2 R41.1
N$52: C50.2 R42.1
N$53: C41.1 C47.1 L4.1 U3.29(OUTPR)
N$54: C65.2 IC21.4(B:O) IC21.6(C:O) IC21.8(D:O)
N$55: C65.1 R242.2
N$56: C67.2 CON1.WL(LEFT:TIP1) R57.1
N$57: C55.1 R43.2
N$58: C56.1 R44.2
N$59: C67.1 R48.2
N$61: C57.1 R45.2
N$62: C58.1 R46.2
N$63: IC21.13(F:I) R48.1 R53.2
N$64: IC21.12(F:O) R53.1 R54.1 R55.1
N$65: IC21.11(E:I) R55.2
N$66: IC21.10(E:O) R56.1
N$74: C66.+ R51.1
N$80: C11.+ R52.1
N$89: C22.1 C36.- R14.1 R88.1
N$90: R89.1 R93.2 U3.14(AM1)
N$119: R91.1 R94.2 U3.15(AM0)
N$120: R90.1 R92.2 U3.13(AM2)
N$121: C39.+ R5.1 U3.11(LINN)
N$122: C20.+ R18.1 U3.10(LINP)
N$232: CON1.RL(LEFT:TIP) R242.1 R243.1
N$245: C221.2 IC21.14(P:VCC) L16.2
OUTN_LEFT: C54.1 L6.2 R46.1 X1.P$4
OUTN_RIGHT: C51.1 L3.2 R44.1 X1.P$2
OUTP_LEFT: C52.1 L5.2 R45.1 X1.P$1
OUTP_RIGHT: C46.1 L4.2 R43.1 X1.P$3
R1: C38.1 R50.1 R51.2 U5.3(R) U$39.8(+IN)
R2: C28.1 IC1.6(B:-IN) R19.1 R31.2 U2.3(R)
R11: R60.2 U5.10(R1)
R12: R59.2 U5.9(R2)
R21: R22.2 U2.10(R1)
R22: R30.2 U2.9(R2)
R2222: C38.2 R23.1 R50.2 R59.1 R60.1 U$39.5(-OUT)
RCAP: IC1.3(A:+IN) R100.2 ; also sheet 1
RIGHT: R12.2 R14.2 ; also sheet 1
SPIN: R56.2 ; also sheet 1
SPOUT: IC21.1(A:I) ; also sheet 1
STBY: R37.2 R101.1 ; also sheet 1
VCC: C59.1 C60.1 C61.+ C62.1 C63.1 C64.+ C74.+ C75.+ R36.2 R92.1 R93.1 R94.1 R95.2 U3.17(AVCC) U3.18(PVCC) U3.19(PVCC) U3.31(PVCC) U3.32(PVCC) ; also sheet 1
VREF: C35.1 C45.2 IC1.5(B:+IN) IC1.10(C:+IN) R10.2 U$39.2(VOCM)
Unconnected: U2.13(CAP_SS) U2.14(3.3V) U3.16(SYNC) U5.13(CAP_SS) U5.14(3.3V)

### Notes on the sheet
- Analog audio inputs | Class-D Power Amplifier
- XLR input voltage ranges: | BTL: 2x40W@8ohm Vcc=26V
- Vin=4Vrms (MUTE=1,SEL=X) | BTL: 2x70W@4ohm Vcc=26V
- Vin=8Vrms (MUTE=0,SEL=1) | PBTL: 1x135W@2ohm Vcc=26V
- Vin=12Vrms (MUTE=0,SEL=0)
- Standby ON: STBY=0
- Standby OFF: STBY=1
- Fc=61kHz
- BTL:R5,R18=NC
- PBTL:R5,R18=0R
- RCA input voltage ranges:
- Vin=1.5Vrms (MUTE=1,SEL=X)
- Vin=3Vrms (MUTE=0,SEL=0) | Gain 20dB: GAIN=1, STBY=0V-PULSE
- Vin=5Vrms (MUTE=0,SEL=1) | Gain 26dB: GAIN=0, STBY=0V-PULSE
- Mute ON: MUTE=0
- Mute OFF: MUTE=1
- Digital audio input+output | Mic

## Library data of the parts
C1-C10 C14-C19 C22-C25 C28-C31 C34 C35 C37 C38 C40-C60 C62 C63 C65 C67-C73 C78-C80 C221 CA1-CA3 CC1-CC5 CD1-CD4 CF1 CH1 CH2 CP1 CR1 CRF1 CRTC1 CSD4 CU3 = rcl:C-EU: CAPACITOR, European symbol
C11-C13 C20 C21 C26 C27 C32 C33 C36 C39 C61 C64 C66 C74-C77 = rcl:CPOL-EU: POLARIZED CAPACITOR, European symbol
CN1 = Omat:CON-USD: Micro SD connector
CN2 = Omat_komponentit:CON_DC-JACK
CN4 CN5 = Omat_komponentit:LIGHT_PIPE4
CON1 = Omat:CON_RCA_2X2
D1 = Omat_komponentit:1N4148: DIODE
D2 = Omat:SS12
D3 = diode:DIODE-: DIODE
F1 = Omat:FUSE_1206
FDC0 FDC1 FDC2 PWM = testpad:PTR1: TEST PIN
GND GND_1 = Omat_komponentit:MEAS_PIN
IC1 = burr-brown:OPA4132: High Speed FET-Input Operational Amplifiers
IC2 = uln-udn:ULN2803A: DRIVER ARRAY
IC21 = 74xx-eu:74*04: Hex INVERTER
JP2 = jumper:JP4E: JUMPER
JP3 JP6 JP9 JP11 MIC = jumper:JP1E: JUMPER
JP4 = pinhead:PINHD-1X8: PIN HEADER
JP5 JP7 JP10 = jumper:JP2E: JUMPER
JP8 = pinhead:PINHD-1X6: PIN HEADER
L1 L2 = Omat:SM-0603: INDUCTOR
L3-L6 = Omat:L_12560
L7 = Omat:L_NR6045
L16 = wuerth-elektronik:WE-KI: SMD Wire Wound Ceramic Inductor WE-KI
LED1-LED8 = led:LED: LED
R1-R101 R242 R243 = rcl:R-EU_: RESISTOR, European symbol
SW1 SW2 = Omat_komponentit:SW_MJTP2205D
T1 = Omat_komponentit:SI2302ADS: MOS FET
T2 = transistor:BC848: NPN TRANSISTOR
U1 = vlsi:VS1005: Multiformat Audio SOC Player IC with USB and NAND FLASH Interface.
U2 U5 = Omat_komponentit:ISL54405
U3 = Omat:TPA3116D2
U4 = Omat:25LCXXXX
U6 = Omat:LM2675
U7 = Omat_komponentit:ZXCL280E5TA
U8 = Omat_komponentit:LM4041CI
U$5 = Omat_komponentit:UA78LXX
U$39 = Omat_kopiot:THS4130
X1 = Omat:TER_BLOCK_4WAY
X2 = Omat_komponentit:CON_USB_B: BERG USB connector Mini USB B smt con: Farnell: 1125348 Molex 675031020 SOCKET, USB MINI-B SMT W/PEGS
X3 = Omat:TER_BLOCK_2WAY
X4 = con-neutrik_ag:NC3: Neutrik Audio Connector XLR SERIES Stereo 1/4" jack Source: www.neutrik.com/
XT1 = Omat:CRYSTAL: CRYSTAL
XT2 = Omat_komponentit:CRYTAL: CRYSTAL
